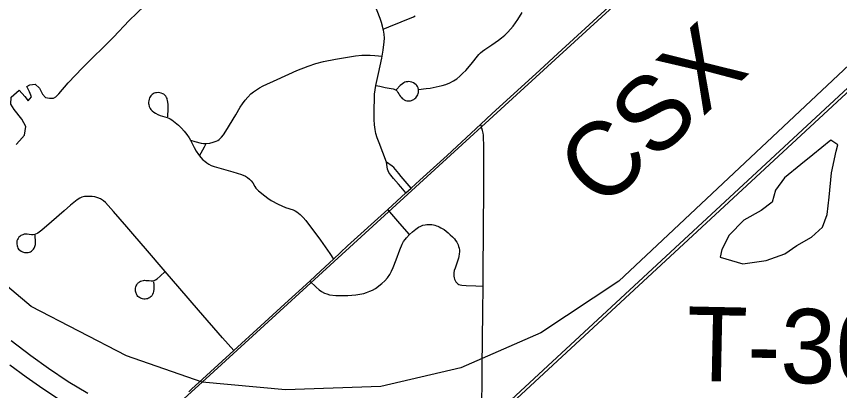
# Model space of a CAD drawing. Extents: x 0 to 34, y 0 to 22.
# Drawn here: x 4.642 to 5.271, y 18.797 to 19.083 of the extents above; entities that cross this region are included whole.
import ezdxf

# ---------------------------------------------------------------- set-up
doc = ezdxf.new("R2010")
doc.units = 0
for name, color, linetype in [('GM_X_Interstate_Route', 7, 'Continuous'), ('GM_X_Major_River', 7, 'Continuous'), ('GM_X_Minor_Lake', 7, 'Continuous'), ('GM_X_Rail_Line', 7, 'Continuous'), ('GM_X_Rail_Line_Text', 7, 'Continuous'), ('GM_X_State_Route', 7, 'Continuous'), ('GM_X_Township_Road', 7, 'Continuous'), ('GM_X_Township_Road_Text', 7, 'Continuous')]:
    doc.layers.add(name, color=color, linetype=linetype)

msp = doc.modelspace()

# ---------------------------------------------------------------- linework, layer by layer
at = {"layer": 'GM_X_Interstate_Route'}
for points in [[(4.63846, 18.83505), (4.65334, 18.82376), (4.66702, 18.81399), (4.68203, 18.80395), (4.69689, 18.79482)], [(4.63739, 18.8166), (4.64987, 18.80738), (4.66256, 18.79845), (4.67765, 18.78864)]]:
    msp.add_lwpolyline(points, dxfattribs=at)
at = {"layer": 'GM_X_Major_River'}
for points in [[(4.68205, 19.03207), (4.69282, 19.04354), (4.71654, 19.06678), (4.72841, 19.07954), (4.74027, 19.09079), (4.75352, 19.09291), (4.7552, 19.10579), (4.76026, 19.11787), (4.77022, 19.12914), (4.77976, 19.13623), (4.79007, 19.14446), (4.80266, 19.1538), (4.81258, 19.16127), (4.8221, 19.16723), (4.84074, 19.17703)], [(4.6422, 18.98494), (4.64488, 18.98756), (4.64871, 18.99207), (4.64955, 18.99851), (4.6466, 19.00424), (4.64064, 19.01152), (4.63805, 19.01573), (4.63849, 19.02103), (4.64461, 19.02627), (4.64888, 19.0215), (4.65131, 19.01823), (4.65399, 19.02123), (4.65253, 19.02504), (4.65031, 19.02924), (4.65259, 19.03035), (4.65676, 19.03106), (4.66012, 19.02798), (4.66233, 19.02341), (4.66457, 19.02072), (4.66758, 19.02031), (4.67061, 19.02027), (4.67251, 19.02139), (4.67481, 19.02364), (4.68205, 19.03207)]]:
    msp.add_lwpolyline(points, dxfattribs=at)
at = {"layer": 'GM_X_Minor_Lake'}
msp.add_line((5.23853, 18.90767), (5.24957, 18.91398), dxfattribs=at)
msp.add_lwpolyline([(5.24957, 18.91398), (5.25798, 18.92184), (5.26151, 18.93129), (5.26319, 18.94455), (5.26494, 18.96312), (5.26856, 18.97978), (5.26976, 18.9847), (5.26451, 18.98818), (5.25077, 18.97697), (5.2416, 18.96949), (5.22901, 18.9594), (5.22208, 18.95), (5.2197, 18.94092), (5.2113, 18.93457), (5.19799, 18.92715), (5.18688, 18.91552), (5.18107, 18.90459), (5.17986, 18.89891), (5.19717, 18.89376), (5.21496, 18.89619), (5.22938, 18.90133), (5.23853, 18.90767)], dxfattribs=at)
at = {"layer": 'GM_X_Rail_Line'}
for points in [[(4.78429, 18.80343), (5.20213, 19.1854), (5.56639, 19.5213), (5.86365, 19.79605), (5.94571, 19.8572), (6.00433, 19.89992), (6.77122, 20.65037), (6.78738, 20.68459), (6.84059, 20.85665), (6.88559, 20.9)], [(4.0369, 17.87629), (4.0405, 17.87963), (4.10582, 17.94022), (4.26502, 18.087), (4.55609, 18.35576), (4.76707, 18.55171), (4.9213, 18.69505), (5.34845, 19.09084), (6.00629, 19.70228), (6.04051, 19.73365)], [(4.26344, 18.0887), (4.5545, 18.35746), (4.76549, 18.55341), (4.91971, 18.69674), (5.34686, 19.09254), (6.00471, 19.70399), (6.03893, 19.73535)], [(6.02958, 19.7244), (6.02241, 19.71974), (5.97395, 19.69027), (5.5555, 19.30184), (5.32439, 19.08907), (5.10249, 18.8805), (5.04303, 18.84113), (4.98191, 18.81432), (4.92078, 18.80008), (4.84793, 18.79757), (4.78429, 18.80343)], [(4.78429, 18.80343), (4.72651, 18.82354), (4.65366, 18.86123), (4.60593, 18.90144), (4.55988, 18.94332), (4.4871, 19.00213)], [(2.20624, 17.40963), (2.27317, 17.34884), (2.53129, 17.30267), (2.6424, 17.31122), (3.24752, 17.60363), (3.90003, 17.91971), (3.99131, 17.98254), (4.33797, 18.26064), (4.40078, 18.3243), (4.44097, 18.38712), (4.46358, 18.43738), (4.47865, 18.49769), (4.49623, 18.5312), (4.52052, 18.56387), (4.5582, 18.59821), (4.78429, 18.80343)]]:
    msp.add_lwpolyline(points, dxfattribs=at)
at = {"layer": 'GM_X_State_Route'}
msp.add_lwpolyline([(4.77415, 18.79589), (4.77625, 18.79791), (4.78767, 18.80851), (4.80843, 18.82743), (4.82904, 18.84623), (4.84738, 18.86304), (4.86649, 18.8806), (4.87487, 18.88829), (4.88462, 18.89736), (4.89537, 18.90735), (4.92601, 18.93528), (4.93977, 18.94783), (4.94393, 18.95163), (4.95054, 18.95765), (4.97126, 18.97648), (4.99711, 19.00042), (5.00549, 19.00818), (5.04224, 19.04172), (5.05586, 19.05448), (5.09491, 19.09015)], dxfattribs=at)
at = {"layer": 'GM_X_Township_Road'}
for points in [[(4.92255, 19.07299), (4.92206, 19.07517), (4.92123, 19.07814), (4.92026, 19.08105), (4.91552, 19.0927), (4.91096, 19.10463), (4.9092, 19.11031), (4.90841, 19.11351), (4.90818, 19.1157), (4.90834, 19.11795), (4.90866, 19.12009), (4.90938, 19.12283), (4.9101, 19.12469), (4.91111, 19.12613), (4.91267, 19.1279)], [(4.9494, 19.02692), (4.95524, 19.02758), (4.95834, 19.02793), (4.9675, 19.02985), (4.97048, 19.03077), (4.97336, 19.03197), (4.97611, 19.03343), (4.97871, 19.03515), (4.98115, 19.0371), (4.98343, 19.03923), (4.98559, 19.04148), (4.98969, 19.04619), (4.99549, 19.05352), (4.99674, 19.05482), (4.99828, 19.05619), (5.0002, 19.05754), (5.00543, 19.06097), (5.01055, 19.06455), (5.013, 19.06647), (5.01538, 19.06849), (5.01765, 19.07064), (5.01978, 19.07291), (5.0218, 19.07529), (5.02369, 19.07777), (5.02542, 19.08036), (5.0286, 19.08574)], [(4.92255, 19.07299), (4.9269, 19.07476), (4.94561, 19.08242), (4.94695, 19.08322)], [(4.92166, 19.05228), (4.92252, 19.05702), (4.9233, 19.06317), (4.92349, 19.06618), (4.92324, 19.06915), (4.92274, 19.07215), (4.92255, 19.07299)], [(4.78737, 18.98566), (4.79023, 18.98592), (4.79263, 18.98654), (4.79484, 18.98737), (4.79614, 18.98799), (4.79724, 18.98874), (4.79903, 18.99039), (4.80056, 18.99234), (4.80232, 18.99499), (4.80989, 19.0076), (4.81333, 19.01338), (4.81505, 19.01593), (4.81718, 19.01882), (4.81911, 19.02109), (4.82151, 19.0235), (4.82357, 19.02515), (4.82577, 19.02673), (4.82818, 19.02818), (4.83087, 19.02956), (4.8416, 19.03459), (4.85653, 19.0413), (4.86517, 19.04468), (4.87101, 19.04663), (4.87696, 19.04819), (4.88605, 19.05004), (4.90133, 19.0526), (4.90633, 19.05305), (4.90943, 19.05312), (4.91266, 19.05319), (4.91624, 19.05292), (4.92166, 19.05228)], [(4.91693, 19.03001), (4.91893, 19.03907), (4.92142, 19.05093), (4.92166, 19.05228)], [(4.92516, 18.97131), (4.91938, 18.9861), (4.91802, 18.98985), (4.91695, 18.99335), (4.91631, 18.9962), (4.9158, 18.99998), (4.91566, 19.00398), (4.91559, 19.00883), (4.91559, 19.01325), (4.9158, 19.01839), (4.91594, 19.02324), (4.91693, 19.03001)], [(4.91693, 19.03001), (4.91989, 19.02938), (4.92404, 19.02843), (4.92706, 19.02793), (4.93026, 19.0274), (4.93102, 19.02722), (4.932, 19.02671), (4.93215, 19.02656), (4.93308, 19.02563), (4.93381, 19.02461), (4.93449, 19.02346), (4.93507, 19.02252), (4.93568, 19.02166), (4.93648, 19.02072), (4.93713, 19.02003), (4.93792, 19.01945), (4.93865, 19.01898), (4.93959, 19.01855), (4.94057, 19.01826), (4.9415, 19.01811), (4.9424, 19.01811), (4.94334, 19.01826), (4.94425, 19.01851), (4.94515, 19.01888), (4.94591, 19.01931), (4.94681, 19.01996), (4.94746, 19.02061), (4.948, 19.02126), (4.94851, 19.02198), (4.9489, 19.02278), (4.9492, 19.02372), (4.94938, 19.02466), (4.94945, 19.02559), (4.9494, 19.02692)], [(4.9494, 19.02692), (4.94912, 19.02824), (4.94872, 19.02914), (4.94821, 19.02986), (4.94767, 19.03047), (4.94681, 19.03116), (4.94569, 19.03188), (4.94435, 19.03242), (4.94305, 19.03275), (4.94191, 19.03288), (4.94099, 19.03282), (4.94004, 19.03264), (4.93911, 19.03237), (4.93822, 19.03193), (4.93733, 19.03133), (4.93548, 19.02987), (4.93257, 19.02698)], [(4.75801, 19.00595), (4.75827, 19.01242), (4.75824, 19.01544), (4.75808, 19.01729), (4.75789, 19.01853), (4.75765, 19.01938), (4.75742, 19.02012), (4.75708, 19.02089), (4.75642, 19.0219), (4.7558, 19.02263), (4.7551, 19.02322), (4.75425, 19.02367), (4.75297, 19.02414), (4.75192, 19.02437), (4.75065, 19.02453), (4.74941, 19.02441), (4.74859, 19.0243), (4.74763, 19.02402), (4.74682, 19.02364), (4.74604, 19.02309), (4.74554, 19.02263), (4.74501, 19.02205), (4.74444, 19.02128), (4.74408, 19.02039), (4.7438, 19.01949), (4.74353, 19.01821), (4.74337, 19.01709), (4.74337, 19.01621), (4.74353, 19.01531), (4.74392, 19.01384), (4.74427, 19.01299), (4.74462, 19.01233), (4.74516, 19.01156), (4.74601, 19.01071), (4.74744, 19.00955), (4.74872, 19.0087), (4.75042, 19.00781), (4.75217, 19.00711), (4.75754, 19.00557), (4.75878, 19.00503), (4.75975, 19.00444), (4.76103, 19.00364), (4.76371, 19.00172), (4.76614, 18.99962), (4.76838, 18.9974), (4.7705, 18.99505), (4.77248, 18.99256), (4.77425, 18.99001), (4.77532, 18.98811)], [(4.99892, 18.87663), (4.99897, 18.87962), (4.99922, 18.92724), (4.99927, 18.94446), (4.99951, 18.98449), (4.99924, 18.98973), (4.99908, 18.99192), (4.99886, 18.99345), (4.99843, 18.99563), (4.99796, 18.99734), (4.99711, 19.00042)], [(4.77532, 18.98811), (4.77582, 18.98723), (4.7782, 18.98247), (4.77972, 18.97982), (4.78138, 18.97732), (4.78226, 18.97613)], [(4.77532, 18.98811), (4.7788, 18.98715), (4.78355, 18.98585), (4.78541, 18.98571), (4.78737, 18.98566)], [(4.78226, 18.97613), (4.78348, 18.97842), (4.78599, 18.98308), (4.78737, 18.98566)], [(4.78226, 18.97613), (4.78319, 18.97487), (4.78477, 18.97326), (4.78636, 18.97205), (4.7878, 18.97091), (4.78938, 18.96986), (4.79112, 18.96895), (4.79354, 18.96804), (4.80768, 18.96402), (4.81433, 18.96185), (4.81728, 18.96057), (4.81879, 18.95959), (4.82045, 18.95831), (4.82182, 18.9571), (4.82295, 18.95566), (4.82446, 18.95279), (4.82529, 18.9516), (4.82733, 18.94942), (4.83206, 18.94565), (4.83452, 18.94387), (4.83706, 18.94219), (4.84241, 18.93924), (4.84512, 18.93791), (4.84793, 18.93682), (4.85371, 18.93486), (4.85538, 18.93421), (4.85661, 18.93338), (4.8592, 18.93144), (4.86146, 18.92916), (4.86347, 18.92671), (4.87458, 18.91169), (4.87825, 18.90672), (4.88002, 18.90421), (4.8817, 18.90171), (4.88462, 18.89736)], [(4.93977, 18.94783), (4.93589, 18.95247), (4.93419, 18.9545), (4.93031, 18.95897), (4.92838, 18.9614), (4.92695, 18.96353), (4.92631, 18.96482), (4.92593, 18.96609), (4.92516, 18.97131)], [(4.94393, 18.95163), (4.93627, 18.96035), (4.93451, 18.96262), (4.93054, 18.96721), (4.92929, 18.96834), (4.92516, 18.97131)], [(4.75607, 18.88776), (4.74093, 18.9054), (4.73286, 18.9149), (4.72675, 18.9219), (4.71663, 18.93366), (4.71248, 18.93828), (4.71036, 18.94047), (4.70881, 18.9419), (4.70671, 18.94326), (4.70449, 18.94425), (4.70239, 18.94486), (4.70029, 18.94517), (4.69838, 18.94523), (4.69653, 18.94523), (4.69443, 18.94505), (4.69246, 18.94455), (4.69073, 18.94375), (4.68876, 18.94257), (4.68382, 18.93856), (4.67883, 18.93424), (4.66921, 18.92591), (4.66181, 18.91943), (4.65867, 18.91709), (4.65654, 18.91607), (4.65529, 18.91588), (4.6539, 18.91588), (4.65219, 18.9161), (4.65052, 18.91628), (4.64952, 18.91634), (4.64845, 18.91628), (4.64732, 18.91591), (4.6459, 18.91523), (4.645, 18.91466), (4.6443, 18.91398), (4.64372, 18.91317), (4.64318, 18.91226), (4.64285, 18.91138), (4.64269, 18.91036), (4.64269, 18.90899), (4.64288, 18.90758), (4.64315, 18.90659), (4.64359, 18.90571), (4.64413, 18.90494), (4.64492, 18.90412), (4.64597, 18.90332), (4.64714, 18.90277), (4.6485, 18.9024), (4.65004, 18.90228), (4.65139, 18.9024), (4.65236, 18.90265), (4.65318, 18.90295), (4.65401, 18.90346), (4.65479, 18.90414), (4.6555, 18.90488), (4.65602, 18.90567), (4.65657, 18.90697), (4.65688, 18.90851), (4.657, 18.91036), (4.65674, 18.91554)], [(4.94259, 18.916), (4.93533, 18.92445), (4.93075, 18.92976), (4.92601, 18.93528)], [(4.94259, 18.916), (4.94487, 18.9182), (4.94738, 18.92023), (4.94942, 18.92163), (4.95129, 18.9226), (4.95291, 18.9232), (4.95457, 18.92358), (4.95597, 18.92375), (4.9572, 18.92384), (4.95848, 18.92384), (4.95971, 18.92372), (4.96095, 18.92354), (4.96209, 18.92321), (4.96324, 18.92278), (4.9643, 18.9224), (4.96536, 18.92193), (4.96656, 18.92134), (4.96758, 18.92078), (4.96902, 18.91985), (4.97052, 18.91874), (4.97221, 18.91738), (4.9738, 18.91592), (4.97553, 18.91433), (4.97702, 18.91271), (4.97787, 18.91152), (4.97868, 18.91037), (4.97932, 18.90922), (4.97979, 18.90812), (4.98017, 18.90693), (4.98047, 18.90556), (4.98068, 18.9042), (4.98068, 18.90293), (4.98059, 18.90148), (4.9803, 18.8994), (4.97996, 18.898), (4.97737, 18.8903), (4.97686, 18.8886), (4.97656, 18.88677), (4.97647, 18.88554), (4.97648, 18.88431), (4.97675, 18.88302), (4.97708, 18.88193), (4.97746, 18.88103), (4.97802, 18.88009), (4.97865, 18.87925), (4.97941, 18.87849), (4.98026, 18.87789), (4.9812, 18.87755), (4.98248, 18.87734), (4.98592, 18.87708), (4.99323, 18.87683), (4.99892, 18.87663)], [(4.86649, 18.8806), (4.87146, 18.87581), (4.87358, 18.87377), (4.87539, 18.87256), (4.87758, 18.87143), (4.8794, 18.87075), (4.88144, 18.87015), (4.88641, 18.86958), (4.89256, 18.86953), (4.89563, 18.86962), (4.90174, 18.87002), (4.90476, 18.87042), (4.90769, 18.87106), (4.90986, 18.87174), (4.91228, 18.87279), (4.91431, 18.87363), (4.91661, 18.87492), (4.92139, 18.8788), (4.92368, 18.88083), (4.92573, 18.88302), (4.92749, 18.88544), (4.92896, 18.88807), (4.93018, 18.89085), (4.93233, 18.89666), (4.93523, 18.90436), (4.9371, 18.90874), (4.93816, 18.91069), (4.93922, 18.91235), (4.94042, 18.91368), (4.94259, 18.916)], [(4.74708, 18.88008), (4.74725, 18.8776), (4.74731, 18.87449), (4.74715, 18.87264), (4.74695, 18.87155), (4.74646, 18.8704), (4.74579, 18.86937), (4.7452, 18.86864), (4.74467, 18.86818), (4.74408, 18.86778), (4.74338, 18.86742), (4.74262, 18.86708), (4.7418, 18.86688), (4.7408, 18.86679), (4.73978, 18.86679), (4.73882, 18.86695), (4.73799, 18.86715), (4.73714, 18.86748), (4.73641, 18.86788), (4.73581, 18.86824), (4.73525, 18.86877), (4.73472, 18.86943), (4.73433, 18.87009), (4.734, 18.87079), (4.73376, 18.87141), (4.73343, 18.87273), (4.73336, 18.87346), (4.73333, 18.87432), (4.73336, 18.87518), (4.73353, 18.87611), (4.73386, 18.87699), (4.73432, 18.87779), (4.73492, 18.87859), (4.73545, 18.87914), (4.73591, 18.87957), (4.7365, 18.87997), (4.7373, 18.88041), (4.73812, 18.8807), (4.73938, 18.881), (4.7403, 18.88113), (4.74126, 18.8811), (4.74229, 18.88103), (4.74387, 18.88087), (4.74539, 18.88073), (4.74648, 18.88067), (4.74754, 18.88093), (4.74861, 18.88147), (4.74985, 18.88226), (4.75214, 18.88428), (4.75607, 18.88776)], [(4.80843, 18.82743), (4.79989, 18.83723), (4.78152, 18.85833), (4.76725, 18.87475), (4.75607, 18.88776)], [(4.99779, 18.78826), (4.99803, 18.80249), (4.99802, 18.81534), (4.99858, 18.85671), (4.99892, 18.87663)]]:
    msp.add_lwpolyline(points, dxfattribs=at)

# ---------------------------------------------------------------- texts
at = {"layer": 'GM_X_Rail_Line_Text'}
msp.add_text('CSX', height=0.056629, rotation=42.93562, dxfattribs=at).set_placement((5.08935, 18.93397))
at = {"layer": 'GM_X_Township_Road_Text'}
msp.add_text('T-304', height=0.056818, rotation=358.81191, dxfattribs=at).set_placement((5.15372, 18.8044))

doc.saveas('drawing.dxf')
